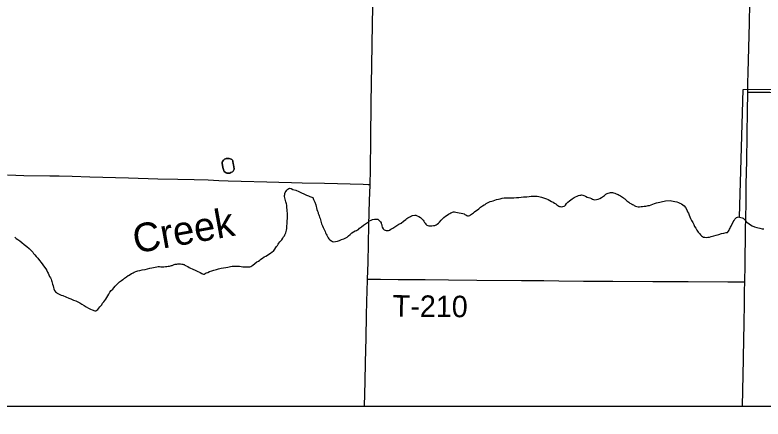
# Model space of a CAD drawing. Extents: x 2.1 to 73.9, y 4 to 26.
# Drawn here: x 43.618 to 44.608, y 20.148 to 20.682 of the extents above; entities that cross this region are included whole.
import ezdxf

# ---------------------------------------------------------------- set-up
doc = ezdxf.new("R2010")
doc.units = 0
for name, color, linetype in [('GM_X_County_Road', 7, 'Continuous'), ('GM_X_Minor_Lake', 7, 'Continuous'), ('GM_X_Minor_Lake_Text', 7, 'Continuous'), ('GM_X_Minor_River', 7, 'Continuous'), ('GM_X_Township_Road', 7, 'Continuous'), ('GM_X_Township_Road_Text', 7, 'Continuous'), ('SH_Text', 7, 'Continuous')]:
    doc.layers.add(name, color=color, linetype=linetype)

msp = doc.modelspace()

# ---------------------------------------------------------------- linework, layer by layer
at = {"layer": 'GM_X_County_Road'}
for points in [[(44.08826, 20.45842), (44.08865, 20.47772), (44.0893, 20.51812), (44.08976, 20.5663), (44.09051, 20.61604), (44.09143, 20.67043), (44.09226, 20.7155), (44.09347, 20.76988), (44.0948, 20.83049), (44.095, 20.83698)], [(44.085, 20.33309), (44.08552, 20.35499), (44.08621, 20.37984), (44.08675, 20.4047), (44.0877, 20.43733), (44.08825, 20.45752), (44.08826, 20.45842)], [(44.08103, 20.16526), (44.08172, 20.19806), (44.08234, 20.22291), (44.08298, 20.25555), (44.08358, 20.28507), (44.08397, 20.30373), (44.08496, 20.33168), (44.085, 20.33309)]]:
    msp.add_lwpolyline(points, dxfattribs=at)
at = {"layer": 'GM_X_Minor_Lake'}
for points in [[(43.90754, 20.48458), (43.90719, 20.48573), (43.90703, 20.48706), (43.90686, 20.48801), (43.90651, 20.48935), (43.90615, 20.49031), (43.90541, 20.49128), (43.90447, 20.49168), (43.90334, 20.49227), (43.90183, 20.4925), (43.90012, 20.49273), (43.89898, 20.49256), (43.89784, 20.49259), (43.89688, 20.49242), (43.89573, 20.49169), (43.89437, 20.49039), (43.89319, 20.48889), (43.89278, 20.48776), (43.89238, 20.48663), (43.89258, 20.4872), (43.89238, 20.48663)], [(43.89238, 20.48663), (43.89258, 20.4872), (43.89238, 20.48663), (43.89278, 20.48776), (43.89319, 20.48889), (43.89437, 20.49039), (43.89573, 20.49169), (43.89688, 20.49242), (43.89784, 20.49259), (43.89898, 20.49256), (43.90012, 20.49273), (43.90183, 20.4925), (43.90334, 20.49227), (43.90447, 20.49168), (43.90541, 20.49128), (43.90615, 20.49031), (43.90651, 20.48935), (43.90686, 20.48801), (43.90703, 20.48706), (43.90719, 20.48573), (43.90754, 20.48458), (43.90771, 20.48363), (43.90805, 20.48191), (43.90822, 20.48096), (43.90839, 20.48), (43.90855, 20.47867), (43.90814, 20.47754), (43.90735, 20.47585), (43.90637, 20.47492), (43.90407, 20.47402), (43.90273, 20.47348), (43.90139, 20.47332), (43.90044, 20.47315), (43.89892, 20.47338), (43.89779, 20.47359), (43.89648, 20.47438), (43.89536, 20.47555), (43.89481, 20.47651), (43.89428, 20.47804), (43.89374, 20.47957), (43.89339, 20.48091), (43.89238, 20.48663)], [(43.89238, 20.48663), (43.89339, 20.48091), (43.89374, 20.47957), (43.89428, 20.47804), (43.89481, 20.47651), (43.89536, 20.47555), (43.89648, 20.47438), (43.89779, 20.47359), (43.89892, 20.47338), (43.90044, 20.47315), (43.90139, 20.47332), (43.90273, 20.47348), (43.90407, 20.47402), (43.90637, 20.47492), (43.90735, 20.47585), (43.90814, 20.47754), (43.90855, 20.47867), (43.90839, 20.48), (43.90822, 20.48096), (43.90805, 20.48191), (43.90771, 20.48363), (43.90754, 20.48458)]]:
    msp.add_lwpolyline(points, dxfattribs=at)
at = {"layer": 'GM_X_Minor_River'}
for points in [[(44.57707, 20.4151), (44.58182, 20.58386), (45.07745, 20.58449)], [(43.92502, 20.34932), (43.9273, 20.34927), (43.92901, 20.34923), (43.93036, 20.34996), (43.93171, 20.35069), (43.93325, 20.35179), (43.93558, 20.35383), (43.93848, 20.35585), (43.94078, 20.35694), (43.94233, 20.35804), (43.94388, 20.35953), (43.94582, 20.361), (43.94813, 20.36247), (43.95025, 20.36375), (43.95256, 20.36503), (43.95449, 20.36632), (43.95661, 20.3676), (43.95874, 20.36907), (43.96047, 20.36998), (43.96145, 20.37129), (43.9646, 20.37634), (43.96578, 20.37784), (43.96676, 20.37933), (43.96774, 20.38064), (43.96892, 20.38232), (43.97029, 20.38381), (43.97146, 20.3853), (43.97284, 20.38736), (43.97383, 20.38924), (43.975, 20.39054), (43.9756, 20.39167), (43.976, 20.3928), (43.97661, 20.3945), (43.97703, 20.3962), (43.97764, 20.39808), (43.97806, 20.39997), (43.97829, 20.40168), (43.97834, 20.40357), (43.97859, 20.40642), (43.97864, 20.40851), (43.97869, 20.41059), (43.97893, 20.41287), (43.97898, 20.41534), (43.97904, 20.41799), (43.97891, 20.42047), (43.97878, 20.42313), (43.97864, 20.42541), (43.97831, 20.42751), (43.97815, 20.42922), (43.978, 20.43074), (43.97766, 20.43265), (43.97731, 20.43399), (43.97697, 20.43552), (43.97643, 20.43724), (43.97609, 20.43895), (43.97556, 20.44068), (43.97522, 20.44239), (43.97506, 20.44354), (43.97528, 20.44486), (43.97569, 20.44618), (43.9761, 20.4475), (43.97709, 20.44938), (43.97826, 20.45087), (43.97924, 20.45218), (43.98078, 20.4529), (43.98231, 20.45325), (43.98382, 20.45284), (43.98627, 20.45183), (43.98985, 20.45061), (43.99381, 20.449), (44.00416, 20.44421), (44.00699, 20.44319), (44.00849, 20.44259), (44.01, 20.44198), (44.01132, 20.44138), (44.01264, 20.44097), (44.01299, 20.43983), (44.01353, 20.43829), (44.01426, 20.43676), (44.0148, 20.4358), (44.01516, 20.43484), (44.01552, 20.43369), (44.01587, 20.43273), (44.01641, 20.4312), (44.01693, 20.4291), (44.01728, 20.42738), (44.01799, 20.42528), (44.01889, 20.42317), (44.01942, 20.42145), (44.01977, 20.41992), (44.02049, 20.41838), (44.02103, 20.41666), (44.02156, 20.41494), (44.02209, 20.41322), (44.02262, 20.4115), (44.02296, 20.40978), (44.02349, 20.40787), (44.02421, 20.40614), (44.0251, 20.40346), (44.0262, 20.40154), (44.02692, 20.39962)], [(44.20156, 20.42168), (44.20383, 20.42144), (44.21102, 20.41995), (44.21253, 20.41935), (44.21384, 20.41856), (44.21516, 20.41796), (44.2161, 20.41737), (44.21704, 20.41696), (44.21836, 20.41675), (44.22009, 20.41747), (44.22106, 20.4182), (44.22241, 20.41912), (44.22395, 20.41985), (44.22492, 20.42078), (44.22647, 20.42207), (44.2284, 20.42355), (44.23033, 20.42483), (44.23208, 20.42631), (44.23421, 20.42835), (44.23711, 20.43019), (44.23903, 20.43128), (44.24038, 20.43201), (44.24174, 20.43312), (44.24347, 20.43422), (44.24539, 20.43513), (44.24731, 20.43565), (44.24922, 20.43618), (44.25114, 20.4369), (44.25324, 20.43761), (44.25554, 20.43832), (44.25822, 20.43902), (44.26051, 20.43953), (44.26299, 20.44005), (44.26586, 20.44055), (44.26871, 20.44068), (44.27175, 20.44061), (44.27499, 20.44073), (44.27841, 20.44084), (44.28184, 20.44095), (44.28507, 20.44107), (44.28812, 20.44138), (44.29136, 20.44187), (44.29555, 20.44216), (44.2986, 20.44247), (44.30146, 20.44279), (44.30431, 20.44272), (44.30678, 20.44286), (44.30925, 20.4428), (44.31134, 20.44256), (44.31323, 20.44214), (44.31493, 20.44172), (44.32153, 20.43929), (44.32398, 20.43829), (44.32624, 20.4371), (44.3283, 20.43591), (44.33037, 20.43473), (44.33224, 20.43354), (44.33393, 20.43256), (44.33524, 20.43158), (44.33655, 20.4306), (44.33786, 20.42981), (44.33899, 20.42921), (44.34012, 20.429), (44.34183, 20.42896), (44.34317, 20.42931), (44.34489, 20.42965), (44.34604, 20.43), (44.34663, 20.43113), (44.34801, 20.43319), (44.34995, 20.43504), (44.35189, 20.43671), (44.35383, 20.43818), (44.35557, 20.43947), (44.35826, 20.44093), (44.36019, 20.44203), (44.3623, 20.44293), (44.36403, 20.44365), (44.36575, 20.44418), (44.36689, 20.44435), (44.36785, 20.44452), (44.36955, 20.4441), (44.37125, 20.44368), (44.37314, 20.44307), (44.37558, 20.44168), (44.37898, 20.44066), (44.38105, 20.43966), (44.38255, 20.43887), (44.38406, 20.43845), (44.38577, 20.43822), (44.38767, 20.43837), (44.38997, 20.43908), (44.39227, 20.43998), (44.39438, 20.44088), (44.39573, 20.4418), (44.39708, 20.44272), (44.39844, 20.44363), (44.40037, 20.4453), (44.40173, 20.44622), (44.40613, 20.44764), (44.40747, 20.4478), (44.40879, 20.44758)], [(44.40879, 20.44758), (44.4105, 20.44735), (44.4122, 20.44693), (44.4137, 20.44614), (44.41521, 20.44553), (44.41634, 20.44494), (44.41784, 20.44415), (44.41953, 20.44316), (44.42103, 20.44236), (44.42234, 20.44158), (44.42347, 20.44079), (44.4244, 20.43982), (44.42533, 20.43923), (44.427, 20.43748), (44.42813, 20.4367), (44.42925, 20.43591), (44.43055, 20.43474), (44.43205, 20.43376), (44.43393, 20.43258), (44.43524, 20.43198), (44.43656, 20.43119), (44.43787, 20.4304), (44.43957, 20.42979), (44.44127, 20.42918), (44.44297, 20.42895), (44.44487, 20.42891), (44.44678, 20.42906), (44.44887, 20.4292), (44.45097, 20.42953), (44.45306, 20.42968), (44.45478, 20.43002), (44.45631, 20.43036), (44.45803, 20.4307), (44.46033, 20.4316), (44.46225, 20.43232), (44.46474, 20.43321), (44.46723, 20.43391), (44.46953, 20.43462), (44.47143, 20.43496), (44.47334, 20.4353), (44.47525, 20.43563), (44.47716, 20.43616), (44.47907, 20.4365), (44.48517, 20.43693), (44.48725, 20.43669), (44.48933, 20.43627), (44.49161, 20.43583), (44.49407, 20.4354), (44.49633, 20.43459), (44.49821, 20.43378), (44.50009, 20.4326), (44.50196, 20.43142), (44.50364, 20.42986), (44.50549, 20.42773), (44.50733, 20.42484), (44.50841, 20.42235), (44.50932, 20.42024), (44.51021, 20.41794), (44.5113, 20.41564), (44.51239, 20.41314), (44.51367, 20.41083), (44.51513, 20.40814), (44.5164, 20.40545), (44.51767, 20.40296), (44.51914, 20.40064), (44.5204, 20.39777), (44.52244, 20.39544), (44.52392, 20.39351), (44.5254, 20.39176), (44.52689, 20.3904), (44.5282, 20.38942), (44.52952, 20.38882), (44.53103, 20.3886), (44.53274, 20.38837), (44.53502, 20.38851), (44.53731, 20.38865), (44.53942, 20.38936), (44.54324, 20.39041), (44.5463, 20.39129), (44.54956, 20.39236), (44.55301, 20.39342), (44.55644, 20.3941), (44.55931, 20.39461), (44.56102, 20.39476), (44.56239, 20.39663), (44.56319, 20.39813), (44.56398, 20.39944), (44.56458, 20.40076), (44.56517, 20.40188), (44.56577, 20.4032), (44.56857, 20.40903), (44.56975, 20.4109), (44.57093, 20.41258), (44.57209, 20.4137), (44.57307, 20.41462), (44.57422, 20.41517), (44.57574, 20.41532), (44.57707, 20.4151), (44.57896, 20.41449), (44.58066, 20.41407), (44.58198, 20.41385)], [(44.02692, 20.39962), (44.02783, 20.39808), (44.02874, 20.39616), (44.02946, 20.39444), (44.03018, 20.39271), (44.03091, 20.39117), (44.03182, 20.38944), (44.03273, 20.3879), (44.03384, 20.38636), (44.03514, 20.385), (44.0372, 20.38362), (44.03871, 20.38302), (44.04003, 20.38261), (44.04518, 20.38325), (44.04786, 20.38414), (44.05055, 20.38541), (44.05362, 20.38667), (44.05611, 20.38775), (44.05804, 20.38866), (44.05979, 20.39052), (44.06192, 20.39218), (44.06405, 20.39422), (44.06637, 20.39569), (44.06868, 20.39696), (44.07041, 20.39768), (44.07175, 20.39841), (44.07291, 20.39896), (44.07446, 20.40044), (44.07678, 20.40229), (44.07968, 20.40431), (44.08239, 20.40615), (44.0849, 20.40799), (44.08625, 20.4091), (44.08742, 20.41003), (44.08992, 20.4113), (44.09164, 20.41183), (44.09393, 20.41235), (44.09602, 20.4123), (44.09736, 20.41246), (44.0985, 20.41243), (44.10017, 20.41088), (44.1011, 20.40991), (44.10203, 20.40874), (44.10276, 20.40778), (44.10312, 20.40663), (44.10365, 20.4051), (44.10381, 20.40358), (44.10434, 20.40166), (44.10562, 20.39974), (44.10674, 20.39857), (44.10806, 20.39797), (44.10957, 20.39756), (44.11128, 20.39752), (44.11261, 20.39768), (44.11395, 20.39803), (44.11588, 20.39912), (44.11819, 20.4004), (44.12611, 20.40592), (44.12918, 20.40737), (44.13266, 20.40995), (44.13575, 20.41216), (44.13711, 20.41327), (44.13827, 20.41419), (44.14154, 20.41602), (44.14327, 20.41674), (44.14461, 20.41728), (44.14728, 20.4176), (44.14899, 20.41756), (44.1505, 20.41695), (44.15257, 20.41615), (44.15482, 20.41477), (44.15687, 20.41301), (44.15835, 20.41127), (44.15927, 20.40973), (44.16019, 20.40819), (44.16111, 20.40703), (44.16185, 20.40606), (44.16353, 20.40469), (44.16465, 20.40391), (44.16617, 20.40368), (44.16807, 20.40364), (44.16997, 20.4036), (44.17207, 20.40393), (44.17398, 20.40427), (44.1757, 20.40498), (44.17724, 20.4059), (44.1786, 20.40701), (44.17997, 20.4085), (44.1823, 20.41091), (44.18405, 20.41277), (44.18599, 20.41444), (44.18813, 20.41629), (44.19006, 20.41777), (44.19218, 20.41905), (44.19372, 20.41996), (44.19507, 20.42088), (44.19642, 20.42142), (44.19737, 20.42178), (44.19871, 20.42213), (44.20004, 20.4221), (44.20156, 20.42168)], [(44.58198, 20.41385), (44.58292, 20.41307), (44.58458, 20.41095), (44.58587, 20.40902), (44.58812, 20.40764), (44.58961, 20.40627), (44.59148, 20.4049), (44.59392, 20.40371), (44.59694, 20.4025), (44.60015, 20.40148), (44.60392, 20.40044), (44.60695, 20.3998), (44.60923, 20.39956)], [(43.61832, 20.38857), (43.62018, 20.38701), (43.62224, 20.38563), (43.62487, 20.38386), (43.62766, 20.38152), (43.63083, 20.37879), (43.63401, 20.37625), (43.63718, 20.37352), (43.6396, 20.37137), (43.64109, 20.36982), (43.64201, 20.36866), (43.64293, 20.36712), (43.6446, 20.36537), (43.64645, 20.36305), (43.64849, 20.36073), (43.65071, 20.35802), (43.65311, 20.35511), (43.65533, 20.35221), (43.65754, 20.34912), (43.65938, 20.34661), (43.66067, 20.34449), (43.66157, 20.34257), (43.6623, 20.34104), (43.66339, 20.33892), (43.6643, 20.33681), (43.66539, 20.3347), (43.6663, 20.33297), (43.66683, 20.33144), (43.66718, 20.32991), (43.66752, 20.32819), (43.66805, 20.32647), (43.66877, 20.32436), (43.66929, 20.32226), (43.67001, 20.32035), (43.67071, 20.31805), (43.6722, 20.3165), (43.67332, 20.31533), (43.67444, 20.31474), (43.67594, 20.31394), (43.67763, 20.31296), (43.67952, 20.31215), (43.68197, 20.31134), (43.68988, 20.30812), (43.69233, 20.30711), (43.69591, 20.30551), (43.69892, 20.30431), (43.70174, 20.3031), (43.70418, 20.30172), (43.70681, 20.29995), (43.70981, 20.29817), (43.71281, 20.29639), (43.71562, 20.29462), (43.71825, 20.29342), (43.72051, 20.29242), (43.72202, 20.292), (43.72297, 20.2916), (43.7241, 20.29139), (43.72543, 20.29117), (43.72697, 20.29208), (43.72794, 20.2932), (43.72931, 20.29469), (43.73087, 20.29655), (43.73204, 20.29786)], [(43.73204, 20.29786), (43.73322, 20.29935), (43.7344, 20.30141), (43.73597, 20.30328), (43.73714, 20.30477), (43.73851, 20.30664), (43.7399, 20.30889), (43.74146, 20.31094), (43.74266, 20.31338), (43.74405, 20.31582), (43.74581, 20.31825), (43.74774, 20.31972), (43.74912, 20.32159), (43.75107, 20.32402), (43.7536, 20.32662), (43.75671, 20.3294), (43.75942, 20.33143), (43.76096, 20.33253), (43.76212, 20.33326), (43.76328, 20.33438), (43.76464, 20.3353), (43.7658, 20.33641), (43.76812, 20.33788), (43.76965, 20.3386), (43.77274, 20.34043), (43.77389, 20.34097), (43.77485, 20.34152), (43.7762, 20.34244), (43.77831, 20.34334), (43.7808, 20.34405), (43.78367, 20.34474), (43.78673, 20.34543), (43.79092, 20.3461), (43.79398, 20.34679), (43.79704, 20.34748), (43.79952, 20.34799), (43.80182, 20.3487), (43.80411, 20.34903), (43.80602, 20.34955), (43.80792, 20.3497), (43.80963, 20.34966), (43.81153, 20.34962), (43.81324, 20.34958), (43.81552, 20.34953), (43.81743, 20.34986), (43.81934, 20.35001), (43.82124, 20.35016), (43.82296, 20.35031), (43.8243, 20.35066), (43.82544, 20.35101), (43.8264, 20.35137), (43.82813, 20.35228), (43.82909, 20.35264), (43.83024, 20.3528), (43.83157, 20.35296), (43.83272, 20.35313), (43.83405, 20.35328), (43.83595, 20.35343), (43.83766, 20.35339), (43.83937, 20.35316), (43.84032, 20.35295), (43.84126, 20.35274), (43.84239, 20.35234), (43.84333, 20.35174), (43.84483, 20.35095), (43.84709, 20.34976), (43.84878, 20.34877), (43.85065, 20.34759), (43.85291, 20.34678), (43.8548, 20.34598), (43.85611, 20.34538), (43.85762, 20.34477), (43.85931, 20.34378), (43.86326, 20.34198), (43.86552, 20.34079), (43.86664, 20.3402), (43.86796, 20.33979), (43.86892, 20.33996), (43.87007, 20.3405), (43.87161, 20.34142), (43.87353, 20.34213), (43.87584, 20.34322), (43.87871, 20.34429), (43.88139, 20.34499), (43.88503, 20.34605), (43.8879, 20.34693), (43.89114, 20.34762), (43.8942, 20.34812), (43.89725, 20.34862), (43.89992, 20.34894), (43.90202, 20.34927), (43.90374, 20.3498), (43.90584, 20.35014), (43.90812, 20.35027), (43.91022, 20.35042), (43.91231, 20.35037), (43.91535, 20.3503), (43.91781, 20.35005), (43.92009, 20.34962), (43.92236, 20.34938), (43.92502, 20.34932)]]:
    msp.add_lwpolyline(points, dxfattribs=at)
at = {"layer": 'GM_X_Township_Road'}
for points in [[(44.58811, 20.58026), (44.58822, 20.59231), (44.58852, 20.60629), (44.59006, 20.67154), (44.5908, 20.69795), (44.59287, 20.79894), (44.59357, 20.82709), (44.59376, 20.83268)], [(44.5841, 20.32966), (44.58413, 20.3313), (44.5844, 20.34995), (44.5846, 20.36237), (44.58498, 20.38723), (44.58516, 20.39965), (44.58545, 20.41364), (44.58571, 20.43383), (44.58596, 20.45869), (44.58654, 20.48976), (44.58749, 20.55658), (44.58809, 20.57833), (44.58811, 20.58026)], [(44.58811, 20.58026), (44.59052, 20.58028), (44.59207, 20.58029), (44.61694, 20.58018), (44.68532, 20.57933), (44.71174, 20.57888), (44.7335, 20.57879), (44.78323, 20.57825), (44.82364, 20.5781), (44.84385, 20.57787), (44.89203, 20.57761), (44.95575, 20.57715), (44.99461, 20.57693), (45.04434, 20.5767), (45.07076, 20.57652), (45.08543, 20.57666)], [(43.60863, 20.47095), (43.61949, 20.4706), (43.63036, 20.47034), (43.66453, 20.46964), (43.67696, 20.46954), (43.69404, 20.46909), (43.71734, 20.46852), (43.7686, 20.46713), (43.80743, 20.46592), (43.83383, 20.46529), (43.85558, 20.46479), (43.87421, 20.46431), (43.88817, 20.46378), (43.90059, 20.46326), (43.91767, 20.46265), (43.95184, 20.46176), (43.96738, 20.46145), (43.98446, 20.46104), (43.99843, 20.46064), (44.02795, 20.45989), (44.04503, 20.45949), (44.06212, 20.45905), (44.0792, 20.45861), (44.08554, 20.45848), (44.08826, 20.45842)], [(44.085, 20.33309), (44.08822, 20.33314), (44.08978, 20.33316), (44.10219, 20.33298), (44.12546, 20.33289), (44.16117, 20.33276), (44.19222, 20.33246), (44.22947, 20.33195), (44.28847, 20.33153), (44.31796, 20.3312), (44.33814, 20.33086), (44.37074, 20.33065), (44.40956, 20.33038), (44.46234, 20.33002), (44.49649, 20.32989), (44.50891, 20.32984), (44.56169, 20.32979), (44.58033, 20.32968), (44.5841, 20.32966)], [(44.5811, 20.16526), (44.58227, 20.22722), (44.58276, 20.25519), (44.58314, 20.27227), (44.58365, 20.30334), (44.58382, 20.31733), (44.5841, 20.32966)]]:
    msp.add_lwpolyline(points, dxfattribs=at)
at = {"layer": 'SH_Text'}
msp.add_lwpolyline([(45.17346, 19.54109), (43.56201, 19.54109), (43.56201, 20.16526), (45.17346, 20.16526)], close=True, dxfattribs=at)

# ---------------------------------------------------------------- texts
at = {"layer": 'GM_X_Minor_Lake_Text'}
msp.add_text('Creek', height=0.037895, rotation=10.19243, dxfattribs=at).set_placement((43.77792, 20.36702))
at = {"layer": 'GM_X_Township_Road_Text'}
msp.add_text('T-210', height=0.028409, rotation=359.4386, dxfattribs=at).set_placement((44.11809, 20.28369))

doc.saveas('drawing.dxf')
